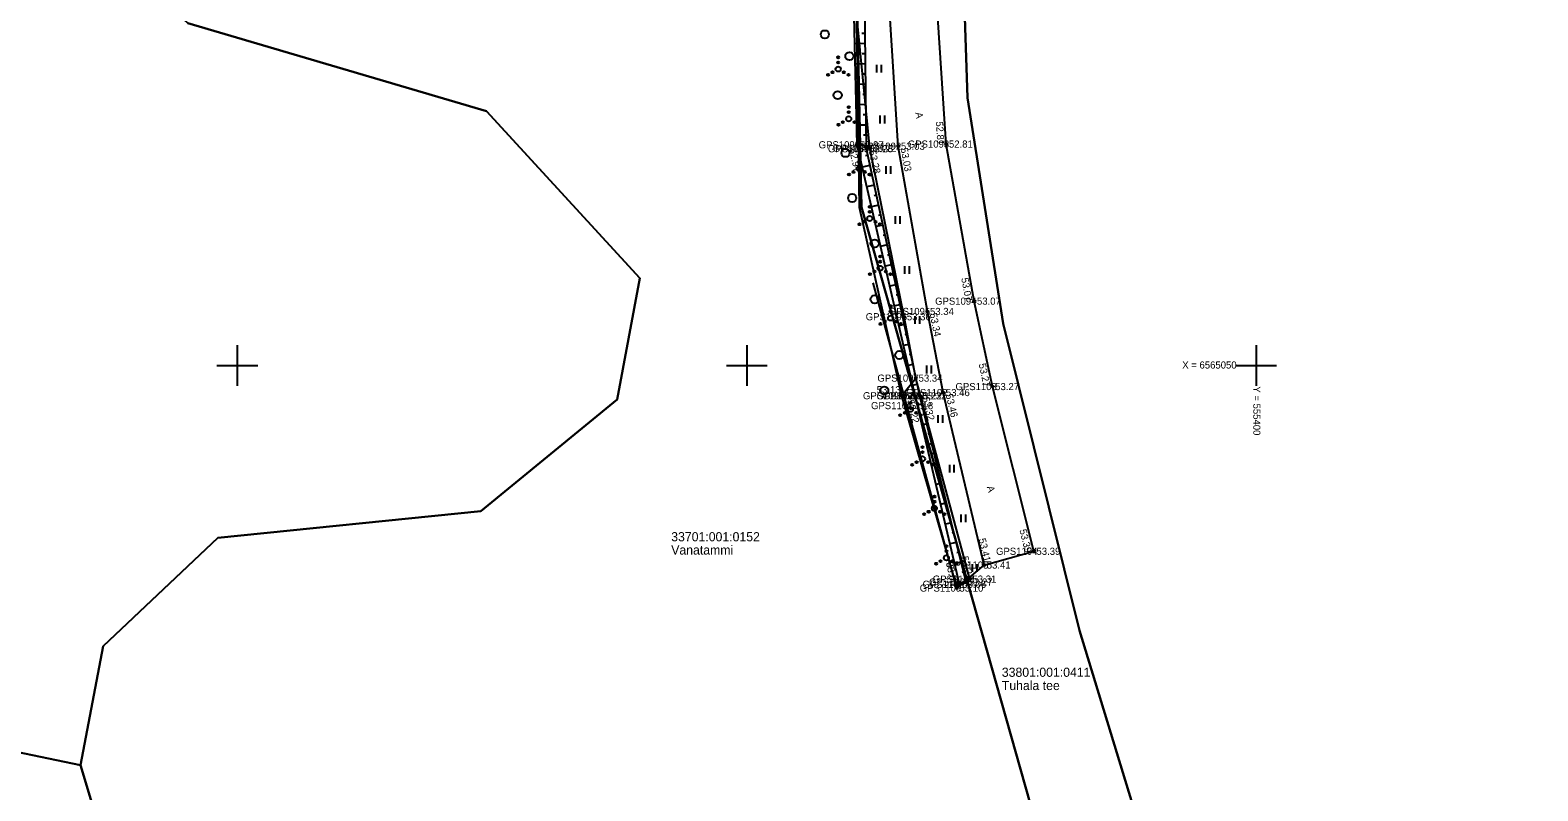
# Model space of a CAD drawing. Extents: x 551623 to 559850, y 6561220 to 6567135.
# Drawn here: x 555279.7 to 555427.7, y 6565008.2 to 6565082.9 of the extents above; entities that cross this region are included whole.
import ezdxf

# ---------------------------------------------------------------- set-up
doc = ezdxf.new("R2010")
doc.units = 0
for name, color, linetype in [('HALJASTUS', 7, 'Continuous'), ('KORGUS-EH2000', 7, 'Continuous'), ('MOOTKORG-EH2000', 7, 'Continuous'), ('MOOTMPUNKT', 7, 'Continuous'), ('MOOTNR', 7, 'Continuous'), ('MOOTPIIR', 7, 'Continuous'), ('MPOHULIIN', 7, 'Continuous'), ('PIIR', 7, 'Continuous'), ('RELJEEF', 7, 'Continuous'), ('TEE', 7, 'Continuous'), ('VORK', 7, 'Continuous')]:
    doc.layers.add(name, color=color, linetype=linetype)

msp = doc.modelspace()

# ---------------------------------------------------------------- linework, layer by layer
at = {"layer": 'HALJASTUS'}
for p, q in [((555362.74, 6565079.52), (555362.74, 6565078.76)), ((555363.2, 6565079.52), (555363.2, 6565078.76)), ((555363.05, 6565074.53), (555363.05, 6565073.77)), ((555363.51, 6565074.53), (555363.51, 6565073.77)), ((555363.64, 6565069.57), (555363.64, 6565068.81)), ((555364.1, 6565069.57), (555364.1, 6565068.81)), ((555364.57, 6565064.66), (555364.57, 6565063.9)), ((555365.03, 6565064.66), (555365.03, 6565063.9)), ((555365.5, 6565059.75), (555365.5, 6565058.99)), ((555365.95, 6565059.75), (555365.95, 6565058.99)), ((555366.51, 6565054.85), (555366.51, 6565054.09)), ((555366.97, 6565054.85), (555366.97, 6565054.09)), ((555371.9, 6565029), (555366.61, 6565048.75)), ((555367.64, 6565049.98), (555367.64, 6565049.22)), ((555368.09, 6565049.98), (555368.09, 6565049.22)), ((555368.76, 6565045.11), (555368.76, 6565044.35)), ((555369.22, 6565045.11), (555369.22, 6565044.35)), ((555369.89, 6565040.24), (555369.89, 6565039.48)), ((555370.34, 6565040.24), (555370.34, 6565039.48)), ((555371.01, 6565035.37), (555371.01, 6565034.6)), ((555371.47, 6565035.37), (555371.47, 6565034.6)), ((555372.14, 6565030.49), (555372.14, 6565029.73)), ((555372.59, 6565030.49), (555372.59, 6565029.73))]:
    msp.add_line(p, q, dxfattribs=at)
msp.add_lwpolyline([(555365.19, 6565047.02), (555366.61, 6565048.75), (555365.46, 6565054.78), (555362.09, 6565071.33), (555360.69, 6565085.61), (555362.06, 6565100.25), (555361.93, 6565109.51), (555364.39, 6565119.3), (555365.03, 6565121.16), (555364.42, 6565124.73), (555359.64, 6565125.97)], dxfattribs=at)
for centre, radius in [((555357.67, 6565082.51), 0.4), ((555358.98, 6565080.26), 0.1), ((555358.98, 6565079.76), 0.1), ((555360.08, 6565080.37), 0.4), ((555357.98, 6565078.54), 0.1), ((555358.41, 6565078.79), 0.1), ((555358.98, 6565079.11), 0.25), ((555359.54, 6565078.79), 0.1), ((555359.98, 6565078.54), 0.1), ((555358.93, 6565076.54), 0.4), ((555360.01, 6565075.37), 0.1), ((555359.01, 6565073.64), 0.1), ((555359.44, 6565073.89), 0.1), ((555360.01, 6565074.22), 0.25), ((555360.01, 6565074.87), 0.1), ((555360.57, 6565073.89), 0.1), ((555361.01, 6565073.64), 0.1), ((555359.7, 6565070.87), 0.4), ((555361.04, 6565069.33), 0.25), ((555361.04, 6565070.48), 0.1), ((555361.04, 6565069.98), 0.1), ((555360.04, 6565068.75), 0.1), ((555360.47, 6565069), 0.1), ((555361.6, 6565069), 0.1), ((555362.04, 6565068.75), 0.1), ((555360.35, 6565066.44), 0.4), ((555362.07, 6565065.58), 0.1), ((555362.07, 6565065.08), 0.1), ((555361.07, 6565063.86), 0.1), ((555361.5, 6565064.11), 0.1), ((555362.07, 6565064.43), 0.25), ((555362.63, 6565064.11), 0.1), ((555363.07, 6565063.86), 0.1), ((555362.56, 6565061.98), 0.4), ((555363.1, 6565060.69), 0.1), ((555362.1, 6565058.97), 0.1), ((555362.53, 6565059.22), 0.1), ((555363.1, 6565059.54), 0.25), ((555363.1, 6565060.19), 0.1), ((555363.66, 6565059.22), 0.1), ((555364.1, 6565058.97), 0.1), ((555362.56, 6565056.49), 0.4), ((555364.13, 6565054.65), 0.25), ((555364.13, 6565055.8), 0.1), ((555364.13, 6565055.3), 0.1), ((555363.13, 6565054.07), 0.1), ((555363.56, 6565054.32), 0.1), ((555364.69, 6565054.32), 0.1), ((555365.13, 6565054.07), 0.1), ((555364.97, 6565051.02), 0.4), ((555363.5, 6565047.53), 0.4), ((555366.07, 6565045.68), 0.25), ((555366.07, 6565046.83), 0.1), ((555366.07, 6565046.33), 0.1), ((555365.07, 6565045.1), 0.1), ((555365.51, 6565045.35), 0.1), ((555366.64, 6565045.35), 0.1), ((555367.07, 6565045.1), 0.1), ((555367.25, 6565041.97), 0.1), ((555367.25, 6565041.47), 0.1), ((555366.25, 6565040.24), 0.1), ((555366.68, 6565040.49), 0.1), ((555367.25, 6565040.82), 0.25), ((555367.81, 6565040.49), 0.1), ((555368.25, 6565040.24), 0.1), ((555368.42, 6565037.11), 0.1), ((555367.42, 6565035.38), 0.1), ((555367.86, 6565035.63), 0.1), ((555368.42, 6565035.96), 0.25), ((555368.42, 6565036.61), 0.1), ((555368.99, 6565035.63), 0.1), ((555369.42, 6565035.38), 0.1), ((555369.6, 6565032.25), 0.1), ((555369.03, 6565030.77), 0.1), ((555369.6, 6565031.1), 0.25), ((555369.6, 6565031.75), 0.1), ((555370.16, 6565030.77), 0.1), ((555368.6, 6565030.52), 0.1), ((555370.6, 6565030.52), 0.1)]:
    msp.add_circle(centre, radius, dxfattribs=at)
at = {"layer": 'KORGUS-EH2000'}
for centre in [(555360.84, 6565071.67), (555361.75, 6565071.28), (555364.88, 6565071.53), (555369.59, 6565071.74), (555372.34, 6565056.31), (555367.73, 6565055.3), (555365.19, 6565047.02), (555366.53, 6565047.01), (555366.99, 6565047.01), (555369.29, 6565047.33), (555374.13, 6565047.92), (555378.18, 6565031.74), (555373.3, 6565030.39), (555370.9, 6565028.5), (555371.53, 6565028.72)]:
    msp.add_circle(centre, 0.1, dxfattribs=at)
at = {"layer": 'MOOTMPUNKT'}
for centre in [(555360.84, 6565071.67), (555361.75, 6565071.28), (555362.09, 6565071.33), (555364.88, 6565071.53), (555369.59, 6565071.74), (555372.34, 6565056.31), (555365.46, 6565054.78), (555367.73, 6565055.3), (555366.61, 6565048.75), (555365.19, 6565047.02), (555366.53, 6565047.01), (555366.99, 6565047.01), (555369.29, 6565047.33), (555374.13, 6565047.92), (555365.7, 6565046.05), (555378.18, 6565031.74), (555373.3, 6565030.39), (555370.62, 6565028.13), (555370.9, 6565028.5), (555371.53, 6565028.72), (555371.9, 6565029)]:
    msp.add_circle(centre, 0.1, dxfattribs=at)
at = {"layer": 'MOOTPIIR'}
msp.add_lwpolyline([(555277.06, 6565106.58), (555292, 6565107.63), (555301.15, 6565108.09), (555306.21, 6565106.2), (555323.3, 6565105.89), (555333.49, 6565106.24), (555356.96, 6565110.39), (555361.34, 6565109.38), (555360.57, 6565097.42), (555361.03, 6565065.55), (555365.19, 6565047.02), (555370.62, 6565028.13), (555373.3, 6565030.39), (555378.18, 6565031.74), (555374.13, 6565047.92), (555372.34, 6565056.31), (555369.59, 6565071.74), (555368.64, 6565086.19), (555368.75, 6565100.14), (555369.59, 6565112.29), (555371.35, 6565124), (555373.31, 6565135.55), (555376.11, 6565151.68), (555380.81, 6565174.03)], dxfattribs=at)
at = {"layer": 'MPOHULIIN'}
msp.add_line((555370.62, 6565028.13), (555362.4, 6565058.1), dxfattribs=at)
at = {"layer": 'PIIR'}
for points in [[(555554.63, 6564988.6), (555394.15, 6564993.09), (555392.11, 6564992.96), (555382.66, 6565023.97), (555375.18, 6565054.1), (555371.67, 6565076.27), (555370.99, 6565097.04), (555372.63, 6565114.59), (555374.63, 6565121.9), (555399.62, 6565240.35), (555402.87, 6565239.66), (555499.25, 6565219.2), (555540.46, 6565411.94)], [(555299.25, 6564626.57), (555283.21, 6564703.33), (555282.17, 6564723.09), (555283.28, 6564740.88), (555283.83, 6564743.87), (555292.4, 6564756.06), (555302.75, 6564765.42), (555370.08, 6564806.46), (555398.67, 6564827.39), (555405.06, 6564834.36), (555414.02, 6564857.57), (555414.37, 6564874.04), (555410.7, 6564895.66), (555382.57, 6564990.22), (555361.28, 6565065.55), (555360.57, 6565097.42), (555362.78, 6565120.42), (555363.12, 6565123.58), (555363.7, 6565126.34), (555385.6, 6565231.48), (555392.88, 6565265.99), (555415.55, 6565372.96)], [(555425.38, 6565362.45), (555399.62, 6565240.35), (555374.63, 6565121.9), (555372.63, 6565114.59), (555370.99, 6565097.04), (555371.67, 6565076.27), (555375.18, 6565054.1), (555382.66, 6565023.97), (555392.11, 6564992.96), (555405.81, 6564947.18), (555420.46, 6564897.93), (555424.39, 6564874.78), (555423.98, 6564855.61), (555413.71, 6564828.99), (555405.37, 6564819.9), (555375.64, 6564798.14), (555308.76, 6564757.38), (555299.94, 6564749.4), (555293.57, 6564740.34), (555292.19, 6564722.96), (555293.16, 6564704.62), (555309.63, 6564625.77)], [(555307.03, 6564911.6), (555306.58, 6564943.93), (555301.69, 6564959.19), (555297.89, 6564966.44), (555284.62, 6565010.72), (555286.82, 6565022.41), (555298.08, 6565033.06), (555323.9, 6565035.68), (555337.29, 6565046.66), (555339.51, 6565058.58), (555324.46, 6565074.96), (555295.15, 6565083.63), (555289.83, 6565088.53), (555288.85, 6565092.31), (555291.54, 6565100.48), (555303.59, 6565115.89), (555332.81, 6565116.31), (555363.12, 6565123.58), (555362.78, 6565120.42), (555360.57, 6565097.42), (555361.28, 6565065.55), (555382.57, 6564990.22), (555410.7, 6564895.66)]]:
    msp.add_lwpolyline(points, dxfattribs=at)
for points in [[(555172.58, 6565163.93), (555173.21, 6565166.35), (555225.89, 6565157.13), (555231.12, 6565150.64), (555239.11, 6565139), (555273.15, 6565087.34), (555275.41, 6565088.83), (555288.85, 6565092.31), (555289.83, 6565088.53), (555295.15, 6565083.63), (555324.46, 6565074.96), (555339.51, 6565058.58), (555337.29, 6565046.66), (555323.9, 6565035.68), (555298.08, 6565033.06), (555286.82, 6565022.41), (555284.62, 6565010.72), (555273.43, 6565013.07), (555140.74, 6565041.04)], [(555133.32, 6565012.53), (555140.74, 6565041.04), (555273.43, 6565013.07), (555284.62, 6565010.72), (555297.89, 6564966.44), (555301.69, 6564959.19), (555306.58, 6564943.93), (555307.03, 6564911.6), (555298.7, 6564900.74), (555277.82, 6564886.76), (555261.15, 6564866.11), (555259.68, 6564861.14), (555249.29, 6564869.43), (555119.68, 6564972.95)]]:
    msp.add_lwpolyline(points, close=True, dxfattribs=at)
at = {"layer": 'RELJEEF'}
for p, q in [((555361.63, 6565081.61), (555360.6, 6565081.6)), ((555361.62, 6565082.61), (555361.31, 6565082.6)), ((555361.65, 6565080.61), (555361.34, 6565080.6)), ((555361.66, 6565079.61), (555360.65, 6565079.6)), ((555361.67, 6565078.61), (555361.37, 6565078.6)), ((555361.68, 6565077.61), (555360.69, 6565077.6)), ((555361.7, 6565075.61), (555360.74, 6565075.6)), ((555361.69, 6565076.61), (555361.4, 6565076.6)), ((555361.71, 6565074.61), (555361.43, 6565074.6)), ((555361.72, 6565073.61), (555360.79, 6565073.6)), ((555361.74, 6565072.61), (555361.46, 6565072.6)), ((555361.75, 6565071.61), (555360.85, 6565071.6)), ((555362.1, 6565069.65), (555361.34, 6565069.48)), ((555361.89, 6565070.62), (555361.66, 6565070.57)), ((555362.31, 6565068.67), (555362.09, 6565068.62)), ((555362.52, 6565067.69), (555361.79, 6565067.53)), ((555362.74, 6565066.71), (555362.52, 6565066.67)), ((555362.95, 6565065.74), (555362.24, 6565065.58)), ((555363.37, 6565063.78), (555362.69, 6565063.63)), ((555363.16, 6565064.76), (555362.95, 6565064.71)), ((555363.58, 6565062.8), (555363.38, 6565062.76)), ((555363.79, 6565061.83), (555363.14, 6565061.69)), ((555364, 6565060.85), (555363.81, 6565060.81)), ((555364.21, 6565059.87), (555363.59, 6565059.74)), ((555364.64, 6565057.92), (555364.04, 6565057.79)), ((555364.42, 6565058.89), (555364.24, 6565058.85)), ((555364.85, 6565056.94), (555364.67, 6565056.9)), ((555365.06, 6565055.96), (555364.49, 6565055.84)), ((555365.27, 6565054.98), (555365.1, 6565054.95)), ((555365.48, 6565054.01), (555364.94, 6565053.89)), ((555365.69, 6565053.03), (555365.53, 6565052.99)), ((555365.9, 6565052.05), (555365.39, 6565051.94)), ((555366.32, 6565050.1), (555365.84, 6565049.99)), ((555366.11, 6565051.07), (555365.96, 6565051.04)), ((555366.54, 6565049.12), (555366.39, 6565049.09)), ((555366.75, 6565048.14), (555366.29, 6565048.04)), ((555366.96, 6565047.16), (555366.83, 6565047.14)), ((555367.19, 6565046.19), (555366.75, 6565046.08)), ((555367.68, 6565044.25), (555367.21, 6565044.14)), ((555367.43, 6565045.22), (555367.3, 6565045.19)), ((555367.92, 6565043.28), (555367.77, 6565043.24)), ((555368.16, 6565042.31), (555367.67, 6565042.19)), ((555368.4, 6565041.34), (555368.25, 6565041.3)), ((555368.64, 6565040.37), (555368.13, 6565040.24)), ((555369.12, 6565038.43), (555368.59, 6565038.3)), ((555368.88, 6565039.4), (555368.72, 6565039.36)), ((555369.36, 6565037.46), (555369.2, 6565037.42)), ((555369.6, 6565036.49), (555369.05, 6565036.35)), ((555369.85, 6565035.52), (555369.67, 6565035.47)), ((555370.09, 6565034.55), (555369.51, 6565034.4)), ((555370.57, 6565032.61), (555369.97, 6565032.46)), ((555370.33, 6565033.58), (555370.15, 6565033.53)), ((555370.81, 6565031.63), (555370.63, 6565031.59)), ((555371.05, 6565030.66), (555370.42, 6565030.51)), ((555371.29, 6565029.69), (555371.1, 6565029.65)), ((555371.53, 6565028.72), (555370.88, 6565028.56))]:
    msp.add_line(p, q, dxfattribs=at)
for points in [[(555370.9, 6565028.5), (555366.53, 6565047.01), (555360.84, 6565071.67), (555360.5, 6565085.72), (555361.15, 6565101.13), (555362.64, 6565109.43), (555363.26, 6565114), (555363.39, 6565114.71)], [(555371.53, 6565028.72), (555366.99, 6565047.01), (555361.75, 6565071.28), (555361.59, 6565085.52), (555361.92, 6565100.78), (555363.31, 6565109.38), (555364.07, 6565113.76), (555363.39, 6565114.71)]]:
    msp.add_lwpolyline(points, dxfattribs=at)
at = {"layer": 'TEE'}
for points in [[(555373.3, 6565030.39), (555369.29, 6565047.33), (555367.73, 6565055.3), (555364.88, 6565071.53), (555363.94, 6565086.13), (555363.94, 6565100.78), (555364.86, 6565113.17), (555366.59, 6565123.44), (555368.58, 6565136.8), (555371.42, 6565152.79), (555376.15, 6565175.29), (555380.89, 6565197.19), (555386.18, 6565222.23), (555388.59, 6565233.37), (555391.03, 6565244.4), (555394.93, 6565263.2), (555398.25, 6565278.79), (555401.56, 6565294.57), (555406.09, 6565316.43), (555410.29, 6565336.28), (555414.12, 6565354.35), (555417.09, 6565367.1)], [(555378.18, 6565031.74), (555374.13, 6565047.92), (555372.34, 6565056.31), (555369.59, 6565071.74), (555368.64, 6565086.19), (555368.75, 6565100.14), (555369.59, 6565112.29), (555371.35, 6565124), (555373.31, 6565135.55), (555376.11, 6565151.68), (555380.81, 6565174.03), (555385.49, 6565196.08), (555390.96, 6565221.1), (555393.17, 6565231.6), (555395.63, 6565243.31), (555399.73, 6565261.92), (555403.12, 6565277.79), (555406.56, 6565293.93), (555410.85, 6565315.26), (555415.01, 6565335.5), (555418.86, 6565352.69), (555421.65, 6565364.94)]]:
    msp.add_lwpolyline(points, dxfattribs=at)
at = {"layer": 'VORK'}
for p, q in [((555300, 6565052), (555300, 6565048)), ((555350, 6565052), (555350, 6565048)), ((555400, 6565052), (555400, 6565048)), ((555298, 6565050), (555302, 6565050)), ((555348, 6565050), (555352, 6565050)), ((555398, 6565050), (555402, 6565050))]:
    msp.add_line(p, q, dxfattribs=at)

# ---------------------------------------------------------------- texts
at = {"layer": 'KORGUS-EH2000'}
for s, rotation, p in [(' 52.81', 273.7402, (555368.55, 6565074.21)), (' 52.97', 282.9989, (555359.98, 6565071.48)), (' 53.28', 282.1848, (555361.92, 6565071.32)), (' 53.03', 279.9561, (555365.06, 6565071.56)), (' 53.07', 280.1224, (555371.01, 6565058.81)), (' 53.34', 281.0598, (555367.91, 6565055.33)), (' 53.27', 282.0415, (555372.71, 6565050.38)), (' 53.46', 283.3207, (555369.46, 6565047.37)), (' 53.22', 283.2793, (555365.68, 6565046.81)), (' 53.32', 283.9507, (555367.16, 6565047.05)), (' 53.39', 284.0621, (555376.7, 6565034.07)), (' 53.41', 283.3207, (555372.7, 6565033.19)), (' 53.27', 283.9507, (555370.99, 6565031.42)), (' 53.06', 283.2793, (555369.48, 6565030.85))]:
    msp.add_text(s, height=0.7, rotation=rotation, dxfattribs=at).set_placement(p)
msp.add_text(' 53.13', height=0.7, dxfattribs=at).set_placement((555362.5, 6565047.26))
at = {"layer": 'MOOTKORG-EH2000'}
for s, p in [(' 52.97', (555360.84, 6565071.32)), (' 53.28', (555361.75, 6565070.93)), (' 53.22', (555362.09, 6565070.98)), (' 53.03', (555364.88, 6565071.18)), (' 52.81', (555369.59, 6565071.39)), (' 53.07', (555372.34, 6565055.96)), (' 53.36', (555365.46, 6565054.43)), (' 53.34', (555367.73, 6565054.95)), (' 53.34', (555366.61, 6565048.4)), (' 53.13', (555365.19, 6565046.67)), (' 53.22', (555366.53, 6565046.66)), (' 53.32', (555366.99, 6565046.66)), (' 53.46', (555369.29, 6565046.98)), (' 53.27', (555374.13, 6565047.57)), (' 53.18', (555365.7, 6565045.7)), (' 53.39', (555378.18, 6565031.39)), (' 53.31', (555371.9, 6565028.66)), (' 53.41', (555373.3, 6565030.04)), (' 53.10', (555370.62, 6565027.78)), (' 53.06', (555370.9, 6565028.15)), (' 53.27', (555371.53, 6565028.37))]:
    msp.add_text(s, height=0.7, dxfattribs=at).set_placement(p)
at = {"layer": 'MOOTNR'}
for s, p in [('GPS1090 ', (555357.06, 6565071.32)), ('GPS1089 ', (555357.97, 6565070.93)), ('GPS1091 ', (555358.45, 6565070.98)), ('GPS1092 ', (555361.1, 6565071.18)), ('GPS1093 ', (555365.81, 6565071.39)), ('GPS1094 ', (555368.49, 6565055.96)), ('GPS1096 ', (555361.68, 6565054.43)), ('GPS1095 ', (555363.95, 6565054.95)), ('GPS1097 ', (555362.83, 6565048.4)), ('GPS1098 ', (555361.41, 6565046.67)), ('GPS1099 ', (555362.75, 6565046.66)), ('GPS1100 ', (555363.35, 6565046.66)), ('GPS1102 ', (555365.65, 6565046.98)), ('GPS1103 ', (555370.49, 6565047.57)), ('GPS1101 ', (555362.2, 6565045.7)), ('GPS1104 ', (555374.47, 6565031.39)), ('GPS1106 ', (555368.26, 6565028.66)), ('GPS1105 ', (555369.66, 6565030.04)), ('GPS1109 ', (555366.98, 6565027.78)), ('GPS1108 ', (555367.26, 6565028.15)), ('GPS1107 ', (555367.89, 6565028.37))]:
    msp.add_text(s, height=0.7, dxfattribs=at).set_placement(p)
at = {"layer": 'PIIR'}
for s, p in [('Vanatammi', (555342.59, 6565031.42)), ('33701:001:0152', (555342.59, 6565032.72)), ('Tuhala tee', (555375.04, 6565018.11)), ('33801:001:0411', (555375.04, 6565019.41))]:
    msp.add_text(s, height=0.9, dxfattribs=at).set_placement(p)
at = {"layer": 'TEE'}
for rotation, p in [(278.9109, (555366.55, 6565074.82)), (285.2418, (555373.56, 6565038.06))]:
    msp.add_text('A', height=0.7, rotation=rotation, dxfattribs=at).set_placement(p)
at = {"layer": 'VORK'}
msp.add_text('X = 6565050', height=0.7, dxfattribs=at).set_placement((555392.75, 6565049.69))
msp.add_text('Y = 555400 ', height=0.7, rotation=270, dxfattribs=at).set_placement((555399.72, 6565047.94))

doc.saveas('drawing.dxf')
